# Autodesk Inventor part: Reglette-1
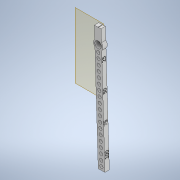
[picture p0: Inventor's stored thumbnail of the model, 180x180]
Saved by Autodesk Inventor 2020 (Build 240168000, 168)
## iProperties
Created: 2022-01
Part Number: Reglette-1
Material: Générique
Document SubType Name: Modeling
Designer: bruno
Density: 1 g/cm^3
Appearance: Par défaut
Author: bruno
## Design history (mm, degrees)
node "Plan de construction1"
sketch "Esquisse1" dims "d7" = 10
  geometry: L1 (14.85, 25.49)-(15.157, 15.867) reference; L2 (8.636, 25.398)-(8.942, 15.775) reference; L3 (11.705, 35.078)-(12.024, 23.082) reference; L4 (12.124, 35.089)-(12.443, 23.093) reference; L5 (12.284, 29.091)-(11.864, 29.08); L6 (14.85, 25.49)-(14.732, 29.189); L7 (14.732, 29.189)-(8.521, 28.991); L8 (8.521, 28.991)-(8.636, 25.398); L9 (8.942, 15.775)-(12.126, -84.11); L10 (12.126, -84.11)-(18.337, -83.912); L11 (18.337, -83.912)-(15.157, 15.867); L12 (11.627, 29.09)-(15.232, -84.011); C1 r 1.5 at (11.787, 24.076); C2 r 1.5 at (11.946, 19.078); C3 r 1.5 at (12.105, 14.081); C4 r 1.5 at (12.264, 9.084); C5 r 1.5 at (12.424, 4.086); C6 r 1.5 at (12.583, -0.911); C7 r 1.5 at (12.742, -5.909); C8 r 1.5 at (12.902, -10.906); C9 r 1.5 at (13.061, -15.904); C10 r 1.5 at (13.22, -20.901); C11 r 1.5 at (13.379, -25.899); C12 r 1.5 at (13.539, -30.896); C13 r 1.5 at (13.698, -35.894); C14 r 1.5 at (13.857, -40.891); C15 r 1.5 at (14.017, -45.889); C16 r 1.5 at (14.176, -50.886); C17 r 1.5 at (14.335, -55.883); C18 r 1.5 at (14.494, -60.881); C19 r 1.5 at (14.654, -65.878); C20 r 1.5 at (14.813, -70.876); C21 r 1.5 at (14.972, -75.873); C22 r 1.5 at (15.132, -80.871); 5 further points
  constraints: 22 centre point, 16 end point, 4 collinear, 4 midpoint, 2 perpendicular, 2 point on line, 43 other
  dimensions: "d0" = 3 diameter of C1; "d1" = 5 distance from line of L5 C1.centre; "d4" = 5 distance of C1.centre C2.centre
extrude "Extrusion1" new body sketch "Esquisse1" distance "d9" = 4; taper "d10" = 0 deg
sketch "Esquisse3"
  geometry: L1 (0.242, -27.359)-(0.242, -23.539); L2 (0.242, -23.539)-(3.511, -23.539); L3 (3.511, -23.539)-(3.511, -27.359); L4 (3.511, -27.359)-(0.242, -27.359); L5 (0.242, -52.298)-(0.242, -47.774); L6 (1.248, -47.774)-(1.248, -52.298); L7 (1.248, -52.298)-(0.242, -52.298); L8 (0.242, -77.299)-(0.242, -72.489); L9 (0.242, -72.489)-(3.526, -72.489); L10 (3.526, -72.489)-(3.526, -77.299); L11 (3.526, -77.299)-(0.242, -77.299); L12 (0.493, -103.681)-(0.493, -101.16); L13 (0.493, -101.16)-(4.215, -101.16); L14 (4.215, -101.16)-(4.215, -103.681); L15 (4.215, -103.681)-(0.493, -103.681); 1 further point; 1 other entity
  constraints: 1 horizontal alignment, 8 other
sketch "Esquisse4"
  geometry: L1 (14.549, 13.544)-(14.646, 16.429) reference; L2 (14.646, 16.429)-(12.196, 17.956) reference; L3 (12.196, 17.956)-(9.649, 16.597) reference; L4 (9.649, 16.597)-(9.552, 13.712) reference; L5 (9.552, 13.712)-(12.002, 12.186) reference; L6 (12.002, 12.186)-(14.549, 13.544) reference; L7 (12.199, 18.06)-(14.737, 16.478); L8 (14.737, 16.478)-(14.637, 13.489); L9 (14.637, 13.489)-(11.998, 12.082); L10 (11.998, 12.082)-(9.46, 13.663); L11 (9.46, 13.663)-(9.56, 16.652); L12 (9.56, 16.652)-(12.199, 18.06); 1 further point
  constraints: 12 end point, 5 other
  node "Référence5"
  node "Référence6"
  node "Référence7"
  node "Référence8"
  node "Référence9"
  node "Référence10"
sketch "Esquisse5"
  geometry: C1 r 1.5 at (11.946, 19.078) reference; C2 r 1.5 at (11.787, 24.076) reference; 1 further point
extrude "Extrusion2" join sketch "Esquisse5" distance "d11" = 3; taper "d12" = 0 deg
extrude "Extrusion3" cut sketch "Esquisse4" distance "d13" = 3; taper "d14" = 0 deg
sketch "Esquisse6"
  geometry: L1 (5.693, 20.183)-(16.686, 20.183); L2 (16.686, 20.183)-(16.686, 11.2); L3 (16.686, 11.2)-(5.693, 11.2); L4 (5.693, 11.2)-(5.693, 20.183); L5 (12.228, 18.019)-(12.053, 12.053); C1 r 4.372 at (12.14, 15.036); C2 r 3.046 at (12.14, 15.036); 3 further points
  constraints: 10 end point, 2 centre point, 2 parallel, 1 coincident, 1 horizontal, 1 midpoint, 1 perpendicular
extrude "Extrusion4" join sketch "Esquisse6" stored distance "d15" = 10; taper "d16" = 0 deg
sketch "Esquisse7"
  geometry: L1 (12.199, 18.06)-(14.737, 16.478) reference; L2 (11.998, 12.082)-(12.199, 18.06); C1 r 3.115 at (12.099, 15.071); 1 further point
  constraints: 2 end point, 1 centre point, 1 midpoint
extrude "Extrusion5" cut sketch "Esquisse7" distance "d17" = 10; taper "d18" = 0 deg
extrude "Extrusion6" cut sketch "Esquisse3" distance "d19" = 0.5; taper "d20" = 0 deg
node "Solide1"
node "Référence1"
node "Référence2"
node "Référence3"
node "Référence4"
